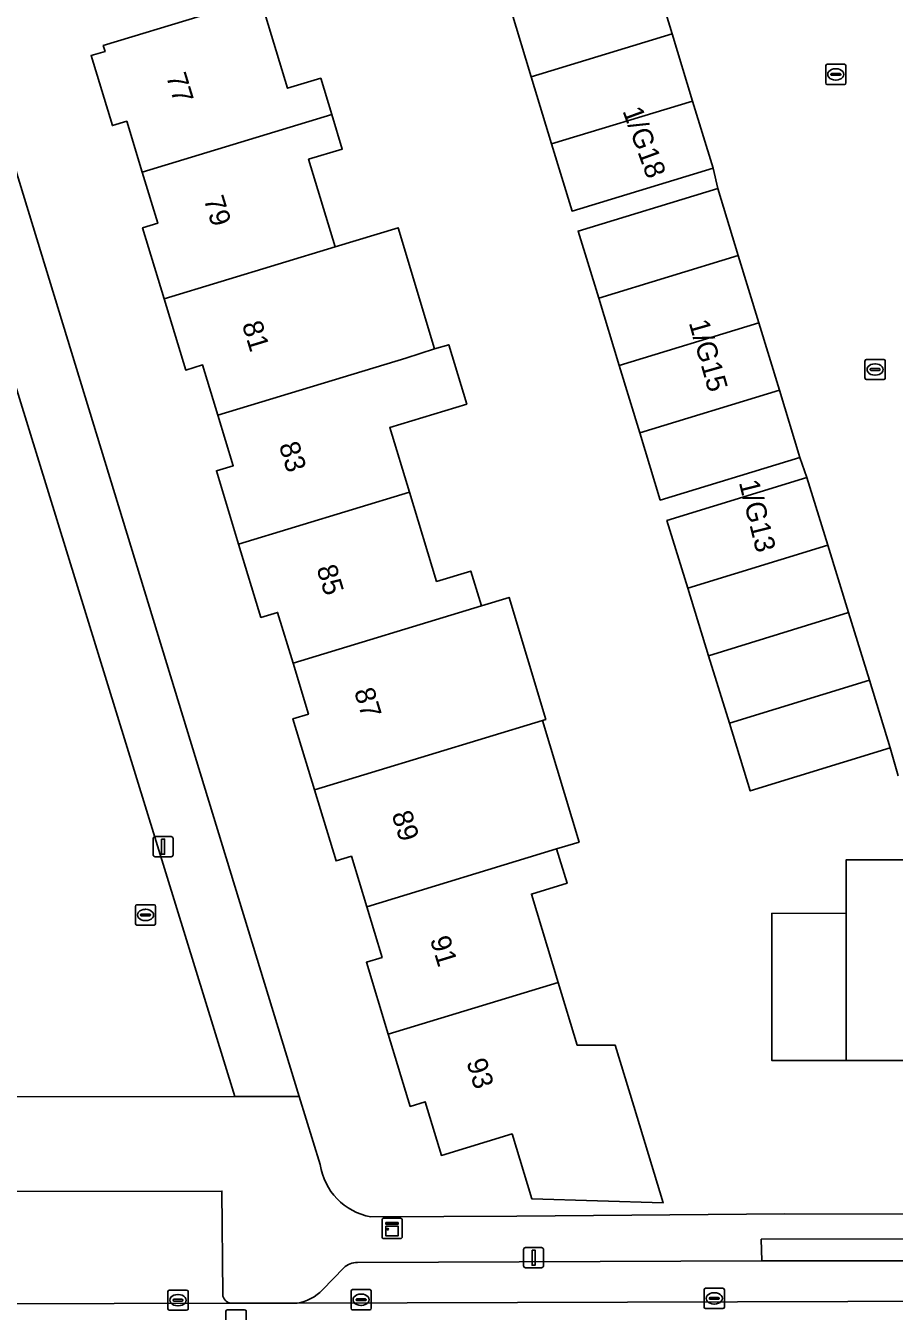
# Model space of a CAD drawing. Extents: x 160732 to 162107, y 387428 to 388479.
# Drawn here: x 161074.3 to 161117.3, y 388134.5 to 388198.1 of the extents above; entities that cross this region are included whole.
import ezdxf

# ---------------------------------------------------------------- set-up
doc = ezdxf.new("R2010")
doc.units = 0
for name, color, linetype in [('IMGEO_Erf', 7, 'Continuous'), ('IMGEO_Groenvoorziening', 7, 'Continuous'), ('IMGEO_Kast', 7, 'Continuous'), ('IMGEO_Kolk', 7, 'Continuous'), ('IMGEO_Lichtmast', 7, 'Continuous'), ('IMGEO_Muur', 7, 'Continuous'), ('IMGEO_Pand', 7, 'Continuous'), ('IMGEO_Pand_nummerreeks', 7, 'Continuous'), ('IMGEO_Parkeervlak_open', 7, 'Continuous'), ('IMGEO_Rijbaan_lokaal_open', 7, 'Continuous'), ('IMGEO_Rioolput', 7, 'Continuous'), ('IMGEO_Voetpad_open', 7, 'Continuous')]:
    doc.layers.add(name, color=color, linetype=linetype)

msp = doc.modelspace()

# ---------------------------------------------------------------- linework, layer by layer
at = {"layer": 'IMGEO_Erf'}
for points in [[(161085.935, 388199.485), (161087.292, 388195.016), (161088.93, 388195.513), (161089.476, 388193.715), (161089.994, 388192.007), (161088.33, 388191.502), (161089.646, 388187.169), (161092.766, 388188.119), (161094.564, 388182.12), (161095.259, 388182.331), (161096.151, 388179.396), (161092.346, 388178.242), (161093.318, 388175.042), (161094.66, 388170.623), (161096.354, 388171.137), (161096.875, 388169.413), (161098.248, 388169.83), (161100.058, 388163.792), (161099.904, 388163.746), (161101.709, 388157.724), (161100.598, 388157.387), (161101.112, 388155.692), (161099.353, 388155.158), (161100.682, 388150.782), (161101.623, 388147.682), (161103.498, 388147.681), (161104.412, 388144.666), (161105.863, 388139.881), (161099.367, 388140.087), (161098.393, 388143.292), (161094.9, 388142.231), (161094.096, 388144.88), (161093.355, 388144.655), (161092.272, 388148.22), (161091.189, 388151.786), (161091.967, 388152.022), (161091.207, 388154.525), (161090.446, 388157.029), (161089.689, 388156.799), (161088.622, 388160.312), (161087.555, 388163.825), (161088.324, 388164.059), (161087.56, 388166.575), (161086.796, 388169.088), (161085.971, 388168.838), (161084.868, 388172.468), (161083.767, 388176.094), (161084.601, 388176.347), (161083.845, 388178.838), (161083.088, 388181.329), (161082.256, 388181.076), (161081.189, 388184.592), (161080.121, 388188.109), (161080.87, 388188.336), (161080.103, 388190.86), (161079.337, 388193.383), (161078.625, 388193.166), (161077.573, 388196.631), (161078.264, 388196.841), (161078.176, 388197.129), (161082.961, 388198.582)], [(161117.499, 388160.997), (161117.103, 388162.395), (161110.179, 388160.26), (161109.148, 388163.602), (161108.117, 388166.944), (161107.086, 388170.287), (161106.055, 388173.63), (161112.979, 388175.765), (161112.634, 388176.758), (161105.728, 388174.648), (161104.712, 388177.975), (161103.695, 388181.301), (161102.679, 388184.628), (161101.662, 388187.955), (161108.568, 388190.065), (161108.334, 388191.062), (161101.363, 388188.94), (161100.352, 388192.261), (161099.34, 388195.583), (161098.329, 388198.904)], [(161071.684, 388197.975), (161087.866, 388145.147), (161088.898, 388141.778)], [(161118.552, 388146.923), (161114.927, 388146.921), (161111.249, 388146.918), (161111.243, 388154.201), (161114.922, 388154.204), (161114.927, 388156.851), (161119.327, 388156.851)], [(161091.402, 388139.194), (161098.635, 388139.224), (161111.891, 388139.34), (161151.971, 388139.278)]]:
    msp.add_lwpolyline(points, dxfattribs=at)
msp.add_arc((161091.976, 388142.255), 3.115, 188.81736, 259.38103, dxfattribs=at)
at = {"layer": 'IMGEO_Groenvoorziening'}
msp.add_lwpolyline([(161071.335, 388145.12), (161084.681, 388145.142), (161070.539, 388190.947)], dxfattribs=at)
at = {"layer": 'IMGEO_Kast'}
for p, q in [((161091.961, 388138.194), (161091.961, 388139.035)), ((161091.961, 388139.035), (161091.961, 388138.194)), ((161092.036, 388139.119), (161092.877, 388139.119)), ((161092.877, 388139.119), (161092.036, 388139.119)), ((161092.961, 388139.044), (161092.961, 388138.203)), ((161092.961, 388138.203), (161092.961, 388139.044)), ((161092.886, 388138.119), (161092.045, 388138.119)), ((161092.045, 388138.119), (161092.886, 388138.119))]:
    msp.add_line(p, q, dxfattribs=at)
for points in [[(161092.156, 388138.909), (161092.756, 388138.909), (161092.756, 388138.824), (161092.156, 388138.824), (161092.156, 388138.909)], [(161092.156, 388138.734), (161092.756, 388138.734), (161092.756, 388138.245), (161092.156, 388138.245), (161092.156, 388138.734)]]:
    msp.add_lwpolyline(points, dxfattribs=at)
msp.add_circle((161092.24, 388138.583), 0.0377, dxfattribs=at)
for centre, start, end in [((161092.039, 388139.041), 92.4484, 184.28452), ((161092.039, 388139.041), 92.4484, 184.28452), ((161092.883, 388139.041), 2.4484, 94.28452), ((161092.883, 388139.041), 2.4484, 94.28452), ((161092.039, 388138.197), 182.4484, 274.28452), ((161092.039, 388138.197), 182.4484, 274.28452), ((161092.883, 388138.197), 272.4484, 4.28452), ((161092.883, 388138.197), 272.4484, 4.28452)]:
    msp.add_arc(centre, 0.0779, start, end, dxfattribs=at)
at = {"layer": 'IMGEO_Kolk'}
for p, q in [((161113.907, 388195.276), (161113.907, 388196.128)), ((161113.982, 388196.202), (161114.834, 388196.202)), ((161114.908, 388196.128), (161114.908, 388195.276)), ((161114.166, 388195.696), (161114.166, 388195.708)), ((161114.604, 388195.659), (161114.206, 388195.659)), ((161114.209, 388195.745), (161114.607, 388195.745)), ((161114.418, 388195.422), (161114.393, 388195.422)), ((161114.395, 388195.982), (161114.42, 388195.982)), ((161114.65, 388195.708), (161114.65, 388195.696)), ((161114.834, 388195.202), (161113.982, 388195.202)), ((161115.852, 388180.678), (161115.852, 388181.53)), ((161115.927, 388181.604), (161116.779, 388181.604)), ((161116.34, 388181.384), (161116.365, 388181.384)), ((161116.853, 388181.53), (161116.853, 388180.678)), ((161116.111, 388181.098), (161116.111, 388181.11)), ((161116.549, 388181.061), (161116.151, 388181.061)), ((161116.154, 388181.147), (161116.552, 388181.147)), ((161116.363, 388180.824), (161116.338, 388180.824)), ((161116.595, 388181.11), (161116.595, 388181.098)), ((161116.779, 388180.604), (161115.927, 388180.604)), ((161107.969, 388135.656), (161108.821, 388135.656)), ((161081.371, 388134.642), (161081.371, 388135.494)), ((161081.446, 388135.568), (161082.298, 388135.568)), ((161081.63, 388135.062), (161081.63, 388135.074)), ((161082.068, 388135.025), (161081.67, 388135.025)), ((161081.673, 388135.111), (161082.071, 388135.111)), ((161081.859, 388135.348), (161081.884, 388135.348)), ((161082.114, 388135.074), (161082.114, 388135.062)), ((161082.372, 388135.494), (161082.372, 388134.642)), ((161090.428, 388134.666), (161090.428, 388135.518)), ((161090.503, 388135.592), (161091.355, 388135.592)), ((161090.687, 388135.086), (161090.687, 388135.098)), ((161091.125, 388135.049), (161090.727, 388135.049)), ((161090.73, 388135.135), (161091.128, 388135.135)), ((161090.916, 388135.372), (161090.941, 388135.372)), ((161091.171, 388135.098), (161091.171, 388135.086)), ((161091.429, 388135.518), (161091.429, 388134.666)), ((161107.894, 388134.73), (161107.894, 388135.582)), ((161108.153, 388135.15), (161108.153, 388135.162)), ((161108.591, 388135.113), (161108.193, 388135.113)), ((161108.196, 388135.199), (161108.594, 388135.199)), ((161108.382, 388135.436), (161108.407, 388135.436)), ((161108.637, 388135.162), (161108.637, 388135.15)), ((161108.895, 388135.582), (161108.895, 388134.73)), ((161082.298, 388134.568), (161081.446, 388134.568)), ((161081.882, 388134.788), (161081.857, 388134.788)), ((161091.355, 388134.592), (161090.503, 388134.592)), ((161090.939, 388134.812), (161090.914, 388134.812)), ((161108.821, 388134.656), (161107.969, 388134.656)), ((161108.405, 388134.876), (161108.38, 388134.876))]:
    msp.add_line(p, q, dxfattribs=at)
for points in [[(161113.907, 388195.276), (161113.907, 388196.128)], [(161113.982, 388196.202), (161114.834, 388196.202)], [(161114.908, 388196.128), (161114.908, 388195.276)], [(161114.834, 388195.202), (161113.982, 388195.202)], [(161115.852, 388180.678), (161115.852, 388181.53)], [(161115.927, 388181.604), (161116.779, 388181.604)], [(161116.853, 388181.53), (161116.853, 388180.678)], [(161116.779, 388180.604), (161115.927, 388180.604)], [(161107.969, 388135.656), (161108.821, 388135.656)], [(161081.371, 388134.642), (161081.371, 388135.494)], [(161081.446, 388135.568), (161082.298, 388135.568)], [(161082.372, 388135.494), (161082.372, 388134.642)], [(161090.428, 388134.666), (161090.428, 388135.518)], [(161090.503, 388135.592), (161091.355, 388135.592)], [(161091.429, 388135.518), (161091.429, 388134.666)], [(161107.894, 388134.73), (161107.894, 388135.582)], [(161108.895, 388135.582), (161108.895, 388134.73)], [(161082.298, 388134.568), (161081.446, 388134.568)], [(161091.355, 388134.592), (161090.503, 388134.592)], [(161108.821, 388134.656), (161107.969, 388134.656)]]:
    msp.add_lwpolyline(points, dxfattribs=at)
for centre, radius, start, end in [((161113.984, 388196.126), 0.0765, 91.55205, 178.44795), ((161113.984, 388196.126), 0.0765, 91.55205, 178.44795), ((161114.832, 388196.126), 0.0765, 1.55205, 88.44795), ((161114.832, 388196.126), 0.0765, 1.55205, 88.44795), ((161114.206, 388195.705), 0.0403, 85.87752, 175.75265), ((161114.203, 388195.695), 0.0366, 178.93798, 274.71019), ((161114.607, 388195.702), 0.043, 264.86636, 352.45326), ((161114.611, 388195.707), 0.0386, 1.73085, 96.63898), ((161113.984, 388195.278), 0.0765, 181.55205, 268.44795), ((161113.984, 388195.278), 0.0765, 181.55205, 268.44795), ((161114.832, 388195.278), 0.0765, 271.55205, 358.44795), ((161114.832, 388195.278), 0.0765, 271.55205, 358.44795), ((161115.929, 388181.528), 0.0765, 91.55205, 178.44795), ((161115.929, 388181.528), 0.0765, 91.55205, 178.44795), ((161116.777, 388181.528), 0.0765, 1.55205, 88.44795), ((161116.777, 388181.528), 0.0765, 1.55205, 88.44795), ((161116.151, 388181.107), 0.0403, 85.87752, 175.75265), ((161116.148, 388181.097), 0.0366, 178.93798, 274.71019), ((161116.552, 388181.104), 0.043, 264.86636, 352.45326), ((161116.556, 388181.109), 0.0386, 1.73085, 96.63898), ((161115.929, 388180.68), 0.0765, 181.55205, 268.44795), ((161115.929, 388180.68), 0.0765, 181.55205, 268.44795), ((161116.777, 388180.68), 0.0765, 271.55205, 358.44795), ((161116.777, 388180.68), 0.0765, 271.55205, 358.44795), ((161107.971, 388135.58), 0.0765, 91.55205, 178.44795), ((161107.971, 388135.58), 0.0765, 91.55205, 178.44795), ((161108.819, 388135.58), 0.0765, 1.55205, 88.44795), ((161108.819, 388135.58), 0.0765, 1.55205, 88.44795), ((161081.448, 388135.492), 0.0765, 91.55205, 178.44795), ((161081.448, 388135.492), 0.0765, 91.55205, 178.44795), ((161081.67, 388135.071), 0.0403, 85.87752, 175.75265), ((161081.667, 388135.061), 0.0366, 178.93798, 274.71019), ((161082.071, 388135.068), 0.043, 264.86636, 352.45326), ((161082.075, 388135.073), 0.0386, 1.73085, 96.63898), ((161082.296, 388135.492), 0.0765, 1.55205, 88.44795), ((161082.296, 388135.492), 0.0765, 1.55205, 88.44795), ((161090.505, 388135.516), 0.0765, 91.55205, 178.44795), ((161090.505, 388135.516), 0.0765, 91.55205, 178.44795), ((161090.727, 388135.095), 0.0403, 85.87752, 175.75265), ((161090.724, 388135.085), 0.0366, 178.93798, 274.71019), ((161091.128, 388135.092), 0.043, 264.86636, 352.45326), ((161091.132, 388135.097), 0.0386, 1.73085, 96.63898), ((161091.353, 388135.516), 0.0765, 1.55205, 88.44795), ((161091.353, 388135.516), 0.0765, 1.55205, 88.44795), ((161108.193, 388135.159), 0.0403, 85.87752, 175.75265), ((161108.19, 388135.149), 0.0366, 178.93798, 274.71019), ((161108.594, 388135.156), 0.043, 264.86636, 352.45326), ((161108.598, 388135.161), 0.0386, 1.73085, 96.63898), ((161081.448, 388134.644), 0.0765, 181.55205, 268.44795), ((161081.448, 388134.644), 0.0765, 181.55205, 268.44795), ((161082.296, 388134.644), 0.0765, 271.55205, 358.44795), ((161082.296, 388134.644), 0.0765, 271.55205, 358.44795), ((161090.505, 388134.668), 0.0765, 181.55205, 268.44795), ((161090.505, 388134.668), 0.0765, 181.55205, 268.44795), ((161091.353, 388134.668), 0.0765, 271.55205, 358.44795), ((161091.353, 388134.668), 0.0765, 271.55205, 358.44795), ((161107.971, 388134.732), 0.0765, 181.55205, 268.44795), ((161107.971, 388134.732), 0.0765, 181.55205, 268.44795), ((161108.819, 388134.732), 0.0765, 271.55205, 358.44795), ((161108.819, 388134.732), 0.0765, 271.55205, 358.44795)]:
    msp.add_arc(centre, radius, start, end, dxfattribs=at)
for centre, major_axis, ratio, start_param, end_param in [((161114.394, 388195.702), (-0.387, 0.002), 0.722429, 4.712389, 7.853982), ((161114.419, 388195.702), (-0.39, 0.002), 0.717154, 1.570796, 4.712389), ((161116.339, 388181.104), (-0.387, 0.002), 0.722429, 4.712389, 7.853982), ((161116.364, 388181.104), (-0.39, 0.002), 0.717154, 1.570796, 4.712389), ((161081.858, 388135.068), (-0.387, 0.002), 0.722429, 4.712389, 7.853982), ((161081.883, 388135.068), (-0.39, 0.002), 0.717154, 1.570796, 4.712389), ((161090.915, 388135.092), (-0.387, 0.002), 0.722429, 4.712389, 7.853982), ((161090.94, 388135.092), (-0.39, 0.002), 0.717154, 1.570796, 4.712389), ((161108.381, 388135.156), (-0.387, 0.002), 0.722429, 4.712389, 7.853982), ((161108.406, 388135.156), (-0.39, 0.002), 0.717154, 1.570796, 4.712389)]:
    msp.add_ellipse(centre, major_axis=major_axis, ratio=ratio, start_param=start_param, end_param=end_param, dxfattribs=at)
at = {"layer": 'IMGEO_Lichtmast'}
for p, q in [((161080.64, 388157.1), (161080.64, 388157.9)), ((161080.64, 388157.9), (161080.64, 388157.1)), ((161080.74, 388158), (161081.53, 388158)), ((161081.53, 388158), (161080.74, 388158)), ((161081.63, 388157.9), (161081.63, 388157.1)), ((161081.63, 388157.1), (161081.63, 388157.9)), ((161081.53, 388157), (161080.74, 388157)), ((161080.74, 388157), (161081.53, 388157)), ((161098.961, 388136.772), (161098.961, 388137.572)), ((161098.961, 388137.572), (161098.961, 388136.772)), ((161099.061, 388137.672), (161099.851, 388137.672)), ((161099.851, 388137.672), (161099.061, 388137.672)), ((161099.951, 388137.572), (161099.951, 388136.772)), ((161099.951, 388136.772), (161099.951, 388137.572)), ((161099.851, 388136.672), (161099.061, 388136.672)), ((161099.061, 388136.672), (161099.851, 388136.672))]:
    msp.add_line(p, q, dxfattribs=at)
for points in [[(161081.06, 388157.875), (161081.21, 388157.875), (161081.21, 388157.125), (161081.06, 388157.125), (161081.06, 388157.875)], [(161099.381, 388137.547), (161099.531, 388137.547), (161099.531, 388136.797), (161099.381, 388136.797), (161099.381, 388137.547)]]:
    msp.add_lwpolyline(points, dxfattribs=at)
for centre, start, end in [((161080.74, 388157.9), 90, 180), ((161080.74, 388157.9), 90, 180), ((161081.53, 388157.9), 0, 90), ((161081.53, 388157.9), 360, 90), ((161080.74, 388157.1), 180, 270), ((161080.74, 388157.1), 180, 270), ((161081.53, 388157.1), 270, 0), ((161081.53, 388157.1), 270, 0), ((161099.061, 388137.572), 90, 180), ((161099.061, 388137.572), 90, 180), ((161099.851, 388137.572), 0, 90), ((161099.851, 388137.572), 360, 90), ((161099.061, 388136.772), 180, 270), ((161099.061, 388136.772), 180, 270), ((161099.851, 388136.772), 270, 0), ((161099.851, 388136.772), 270, 0)]:
    msp.add_arc(centre, 0.1, start, end, dxfattribs=at)
at = {"layer": 'IMGEO_Muur'}
msp.add_lwpolyline([(161111.891, 388139.34), (161098.635, 388139.224)], dxfattribs=at)
at = {"layer": 'IMGEO_Pand'}
for points in [[(161105.3, 388201.027), (161098.329, 388198.904), (161099.34, 388195.583), (161106.311, 388197.705)], [(161089.476, 388193.715), (161088.93, 388195.513), (161087.292, 388195.016), (161085.935, 388199.485), (161082.961, 388198.582), (161078.176, 388197.129), (161078.264, 388196.841), (161077.573, 388196.631), (161078.625, 388193.166), (161079.337, 388193.383), (161080.103, 388190.86)], [(161106.311, 388197.705), (161099.34, 388195.583), (161100.352, 388192.261), (161107.323, 388194.384)], [(161107.323, 388194.384), (161100.352, 388192.261), (161101.363, 388188.94), (161108.334, 388191.062)], [(161089.646, 388187.169), (161088.33, 388191.502), (161089.994, 388192.007), (161089.476, 388193.715), (161080.103, 388190.86), (161080.87, 388188.336), (161080.121, 388188.109), (161081.189, 388184.592)], [(161108.568, 388190.065), (161101.662, 388187.955), (161102.679, 388184.628), (161109.584, 388186.738)], [(161094.564, 388182.12), (161092.766, 388188.119), (161089.646, 388187.169), (161081.189, 388184.592), (161082.256, 388181.076), (161083.088, 388181.329), (161083.845, 388178.838), (161093.145, 388181.671)], [(161109.584, 388186.738), (161102.679, 388184.628), (161103.695, 388181.301), (161110.601, 388183.412)], [(161110.601, 388183.412), (161103.695, 388181.301), (161104.712, 388177.975), (161111.618, 388180.085)], [(161094.564, 388182.12), (161093.145, 388181.671), (161083.845, 388178.838), (161084.601, 388176.347), (161083.767, 388176.094), (161084.868, 388172.468), (161093.318, 388175.042), (161092.346, 388178.242), (161096.151, 388179.396), (161095.259, 388182.331)], [(161111.618, 388180.085), (161104.712, 388177.975), (161105.728, 388174.648), (161112.634, 388176.758)], [(161112.979, 388175.765), (161106.055, 388173.63), (161107.086, 388170.287), (161114.01, 388172.422)], [(161084.868, 388172.468), (161085.971, 388168.838), (161086.796, 388169.088), (161087.56, 388166.575), (161096.875, 388169.413), (161096.354, 388171.137), (161094.66, 388170.623), (161093.318, 388175.042)], [(161114.01, 388172.422), (161107.086, 388170.287), (161108.117, 388166.944), (161115.041, 388169.08)], [(161099.904, 388163.746), (161100.058, 388163.792), (161098.248, 388169.83), (161096.875, 388169.413), (161087.56, 388166.575), (161088.324, 388164.059), (161087.555, 388163.825), (161088.622, 388160.312)], [(161115.041, 388169.08), (161108.117, 388166.944), (161109.148, 388163.602), (161116.072, 388165.738)], [(161116.072, 388165.738), (161109.148, 388163.602), (161110.179, 388160.26), (161117.103, 388162.395)], [(161100.598, 388157.387), (161101.709, 388157.724), (161099.904, 388163.746), (161088.622, 388160.312), (161089.689, 388156.799), (161090.446, 388157.029), (161091.207, 388154.525)], [(161091.207, 388154.525), (161091.967, 388152.022), (161091.189, 388151.786), (161092.272, 388148.22), (161100.682, 388150.782), (161099.353, 388155.158), (161101.112, 388155.692), (161100.598, 388157.387)], [(161125.122, 388154.851), (161119.327, 388154.851), (161119.327, 388156.851), (161114.927, 388156.851), (161114.922, 388154.204), (161114.927, 388146.921), (161118.552, 388146.923), (161118.554, 388144.254), (161125.122, 388144.259), (161125.113, 388152.259), (161125.111, 388153.956)], [(161114.927, 388146.921), (161114.922, 388154.204), (161111.243, 388154.201), (161111.249, 388146.918)], [(161092.272, 388148.22), (161093.355, 388144.655), (161094.096, 388144.88), (161094.9, 388142.231), (161098.393, 388143.292), (161099.367, 388140.087), (161105.863, 388139.881), (161104.412, 388144.666), (161103.498, 388147.681), (161101.623, 388147.682), (161100.682, 388150.782)]]:
    msp.add_lwpolyline(points, close=True, dxfattribs=at)
at = {"layer": 'IMGEO_Parkeervlak_open'}
for points in [[(161084.081, 388135.347), (161084.044, 388140.461), (161061.422, 388140.438), (161061.45, 388134.853), (161084.468, 388134.923)], [(161110.754, 388137.021), (161090.746, 388136.938)], [(161119.782, 388137.014), (161110.754, 388137.021)], [(161090.075, 388136.668), (161089.023, 388135.578)], [(161087.767, 388134.917), (161147.688, 388135.104)]]:
    msp.add_lwpolyline(points, dxfattribs=at)
for centre, radius, start, end in [((161090.764, 388135.924), 1.014, 91.03015, 132.80803), ((161084.562, 388135.397), 0.483, 185.94913, 258.82652), ((161087.332, 388137.267), 2.39, 280.48226, 315.03107)]:
    msp.add_arc(centre, radius, start, end, dxfattribs=at)
at = {"layer": 'IMGEO_Rijbaan_lokaal_open'}
for points in [[(161105.3, 388201.027), (161106.311, 388197.705), (161107.323, 388194.384), (161108.334, 388191.062), (161108.568, 388190.065), (161109.584, 388186.738), (161110.601, 388183.412), (161111.618, 388180.085), (161112.634, 388176.758), (161112.979, 388175.765), (161114.01, 388172.422), (161115.041, 388169.08), (161116.072, 388165.738), (161117.103, 388162.395), (161117.499, 388160.997)], [(161147.688, 388135.104), (161087.767, 388134.917)], [(161084.468, 388134.923), (161061.45, 388134.853)], [(161087.767, 388134.917), (161084.468, 388134.923)]]:
    msp.add_lwpolyline(points, dxfattribs=at)
at = {"layer": 'IMGEO_Rioolput'}
for p, q in [((161079.763, 388153.696), (161079.763, 388154.548)), ((161079.838, 388154.622), (161080.69, 388154.622)), ((161080.022, 388154.116), (161080.022, 388154.128)), ((161080.46, 388154.079), (161080.062, 388154.079)), ((161080.065, 388154.165), (161080.463, 388154.165)), ((161080.251, 388154.402), (161080.276, 388154.402)), ((161080.506, 388154.128), (161080.506, 388154.116)), ((161080.764, 388154.548), (161080.764, 388153.696)), ((161080.69, 388153.622), (161079.838, 388153.622)), ((161080.274, 388153.842), (161080.249, 388153.842)), ((161084.24, 388133.667), (161084.24, 388134.519)), ((161084.315, 388134.593), (161085.167, 388134.593)), ((161085.241, 388134.519), (161085.241, 388133.667))]:
    msp.add_line(p, q, dxfattribs=at)
for points in [[(161079.763, 388153.696), (161079.763, 388154.548)], [(161079.838, 388154.622), (161080.69, 388154.622)], [(161080.764, 388154.548), (161080.764, 388153.696)], [(161080.69, 388153.622), (161079.838, 388153.622)], [(161084.24, 388133.667), (161084.24, 388134.519)], [(161084.315, 388134.593), (161085.167, 388134.593)], [(161085.241, 388134.519), (161085.241, 388133.667)]]:
    msp.add_lwpolyline(points, dxfattribs=at)
for centre, radius, start, end in [((161079.84, 388154.546), 0.0765, 91.55205, 178.44795), ((161079.84, 388154.546), 0.0765, 91.55205, 178.44795), ((161080.062, 388154.125), 0.0403, 85.87752, 175.75265), ((161080.059, 388154.115), 0.0366, 178.93798, 274.71019), ((161080.463, 388154.122), 0.043, 264.86636, 352.45326), ((161080.467, 388154.127), 0.0386, 1.73085, 96.63898), ((161080.688, 388154.546), 0.0765, 1.55205, 88.44795), ((161080.688, 388154.546), 0.0765, 1.55205, 88.44795), ((161079.84, 388153.698), 0.0765, 181.55205, 268.44795), ((161079.84, 388153.698), 0.0765, 181.55205, 268.44795), ((161080.688, 388153.698), 0.0765, 271.55205, 358.44795), ((161080.688, 388153.698), 0.0765, 271.55205, 358.44795), ((161084.317, 388134.517), 0.0765, 91.55205, 178.44795), ((161084.317, 388134.517), 0.0765, 91.55205, 178.44795), ((161085.165, 388134.517), 0.0765, 1.55205, 88.44795), ((161085.165, 388134.517), 0.0765, 1.55205, 88.44795)]:
    msp.add_arc(centre, radius, start, end, dxfattribs=at)
for centre, major_axis, ratio, start_param, end_param in [((161080.25, 388154.122), (-0.387, 0.002), 0.722429, 4.712389, 7.853982), ((161080.275, 388154.122), (-0.39, 0.002), 0.717154, 1.570796, 4.712389)]:
    msp.add_ellipse(centre, major_axis=major_axis, ratio=ratio, start_param=start_param, end_param=end_param, dxfattribs=at)
at = {"layer": 'IMGEO_Voetpad_open'}
for points in [[(161070.256, 388191.862), (161070.539, 388190.947), (161084.681, 388145.142), (161087.866, 388145.147), (161071.684, 388197.975)], [(161087.866, 388145.147), (161084.681, 388145.142), (161071.335, 388145.12), (161060.488, 388145.102), (161060.489, 388142.917), (161061.422, 388140.438), (161084.044, 388140.461), (161084.081, 388135.347)], [(161088.898, 388141.778), (161087.866, 388145.147)], [(161151.971, 388139.278), (161111.891, 388139.34), (161098.635, 388139.224), (161091.402, 388139.194)], [(161090.746, 388136.938), (161110.754, 388137.021), (161110.72, 388138.081), (161119.766, 388138.111), (161119.782, 388137.014), (161144.962, 388137.01)], [(161089.023, 388135.578), (161090.075, 388136.668)], [(161084.468, 388134.923), (161087.767, 388134.917)]]:
    msp.add_lwpolyline(points, dxfattribs=at)
msp.add_lwpolyline([(161110.754, 388137.021), (161119.782, 388137.014), (161119.766, 388138.111), (161110.72, 388138.081)], close=True, dxfattribs=at)
for centre, radius, start, end in [((161091.976, 388142.255), 3.115, 188.81736, 259.38103), ((161090.764, 388135.924), 1.014, 91.03015, 132.80803), ((161084.562, 388135.397), 0.483, 185.94913, 258.82652), ((161087.332, 388137.267), 2.39, 280.48226, 315.03107)]:
    msp.add_arc(centre, radius, start, end, dxfattribs=at)

# ---------------------------------------------------------------- texts
at = {"layer": 'IMGEO_Pand_nummerreeks'}
for s, rotation, p in [('77', 286.99293, (161081.275, 388195.614)), ('1/G18', 290.1363, (161103.846, 388193.896)), ('79', 286.99293, (161083.134, 388189.53)), ('81', 286.99293, (161085.026, 388183.338)), ('1/G15', 285.9454, (161107.13, 388183.424)), ('83', 286.99372, (161086.852, 388177.363)), ('1/G13', 284.03624, (161109.608, 388175.521)), ('85', 286.99293, (161088.712, 388171.278)), ('87', 286.99293, (161090.571, 388165.194)), ('89', 286.99293, (161092.43, 388159.11)), ('91', 286.99293, (161094.323, 388152.918)), ('93', 286.88361, (161096.128, 388146.862))]:
    msp.add_text(s, height=1, rotation=rotation, dxfattribs=at).set_placement(p)

doc.saveas('drawing.dxf')
